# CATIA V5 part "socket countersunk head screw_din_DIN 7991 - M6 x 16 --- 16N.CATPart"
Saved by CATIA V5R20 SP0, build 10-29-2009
Part number: socket countersunk head screw_din_DIN 7991 - M6 x 16 --- 16N
Revision: ANY
Definition: UNKNOWN
Nomenclature: socket countersunk head screw_din_DIN 7991 - M6 x 16 --- 16N
Source: Unknown
Bounding box of the stored display mesh (mm): x 0 to 16, y -5.785 to 5.785, z -5.785 to 5.785
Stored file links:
  C:\Users\Utente\Desktop\IO LAVORO\3D X SITO CF\CUMSA\3D files GR\GR 222826-10\socket countersunk head screw_din_DIN 7991 - M6 x 16 --- 16N.CATPart
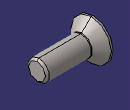
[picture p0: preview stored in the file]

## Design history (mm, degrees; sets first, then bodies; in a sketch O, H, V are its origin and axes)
Body1 "Hex" (main body)
  Solid1: solid without history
